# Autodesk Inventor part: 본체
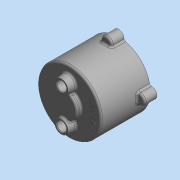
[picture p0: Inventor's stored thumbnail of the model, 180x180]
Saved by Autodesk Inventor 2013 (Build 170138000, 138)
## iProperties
Created: 2015-11
Part Number: 본체
Document SubType Name: 모델링
Designer: mdu
Material: 알루미늄 6061
Density: 2.71 g/cm^3
Mass: 464.622 g
Surface Area: 669.592 cm^2
Volume: 171.447 cm^3
변환 표준: STEP AP214IS
파일 이름: C:\Users\SeoGD\Desktop\?쒗뿕\紐몄껜.stp
전처리기: Build: 253, Release: 2010 SP1 - Date: Wed 07/29/2009
전송 단위: 밀리미터
불확실성: 0.01
Author: mdu
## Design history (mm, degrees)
sketch "스케치2"
  geometry: C1 r 50 at (0, 0); 1 further point
  constraints: 1 centre point, 1 coincident
  dimensions: "d9" = 100 diameter of C1
extrude "돌출2" new body sketch "스케치2" distance "d10" = 78.5; taper "d11" = 0 deg
feature "쉘1" dims "d12" = 5
sketch "스케치3" dims "d13" = 55
  geometry: C1 r 7.5 at (0, 27.5); C2 r 12.5 at (0, 27.5); 2 further points
  constraints: 2 centre point, 2 coincident, 2 vertical alignment, 2 other
  dimensions: "d14" = 15 diameter of C1; "d15" = 25 diameter of C2
extrude "돌출3" join sketch "스케치3" distance "d16" = 12; taper "d17" = -10 deg
hole "구멍2" diameter "d20" = 15; stored, may be unused: countersink angle "d24" = 90 deg, drill point angle "d26" = 118 deg; dims "d18" = 10, "d19" = 10, "d21" = 6, "d22" = 4, "d23" = 2, "d25" = 15
chamfer "모따기1" distance "d27" = 1; stored, may be unused: second distance "d28" = 2, angle "d29" = 45 deg
sketch "스케치4"
  geometry: L1 (0, 0)-(0, 86.5); L2 (0, 68.5)-(13.16, 68.5); L3 (-45, 73.5)-(45, 73.5) reference; L4 (-50, 78.5)-(50, 78.5) reference; L5 (13.16, 68.5)-(14.5, 73.5); L6 (20, 78.5)-(20, 86.5); L7 (20, 86.5)-(0, 86.5); L8 (20, 78.5)-(14.5, 73.5)
  constraints: 12 end point, 3 point on line, 2 perpendicular, 1 vertical
  dimensions: "d34" = 40 diameter of L6 L1; "d35" = 105 deg angle of L5 L3; "d36" = 5 distance between parallel lines of L2 L3; "d37" = 8 distance between parallel lines of L7 L4; "d51" = 29 diameter of L5.end L1
revolve "회전1" sketch "스케치4" stored, may be unused: angle "d38" = 90 deg
hole "구멍3" diameter "d41" = 15; stored, may be unused: countersink angle "d45" = 90 deg, drill point angle "d47" = 0 deg; dims "d39" = 10, "d40" = 10, "d42" = 6, "d43" = 22, "d44" = 13, "d46" = 15
chamfer "모따기2" distance "d48" = 1; stored, may be unused: second distance "d49" = 2, angle "d50" = 45 deg
fillet "모깎기1" dims "d52" = 3
fillet "모깎기2" dims "d53" = 3, "d72" = 0.2
sketch "스케치5"
  geometry: A1 r 50 centre (0, 0) between (50, 0) and (-8.074, 49.344) reference; A2 r 8.5 centre (0, 52) between (8.074, 49.344) and (-8.074, 49.344); 1 further point
  constraints: 5 point on circle, 1 centre point, 1 horizontal alignment
  dimensions: "d54" = 90 deg dimension on point (0, 0) A2.centre A1.start; "d55" = 52 distance of A2.centre point (0, 0); "d56" = 17 diameter of A2
extrude "돌출4" join sketch "스케치5" distance "d57" = 20; taper "d58" = 0 deg
fillet "모깎기3" dims "d59" = 3
hole "구멍4" diameter "d62" = 4.134; stored, may be unused: countersink angle "d66" = 90 deg, drill point angle "d68" = 118 deg; dims "d60" = 10, "d61" = 10, "d63" = 12, "d64" = 22, "d65" = 13, "d67" = 15
sketch "스케치6"
  geometry: C1 r 47 at (0, 0) reference; C2 r 42.5 at (0, 0); 1 further point
  constraints: 1 centre point, 1 coincident, 1 other
  dimensions: "d73" = 85 diameter of C2
feature "엠보싱1" sketch "스케치6" dims "d74" = 0.5, "d75" = 0
node "솔리드1"
node "솔리드 본체"
node "곡면 본체"
pattern_circular "원형 패턴1" dims "d31" = 360 deg
pattern_circular "원형 패턴2" dims "d70" = 360 deg
node "솔리드2"
